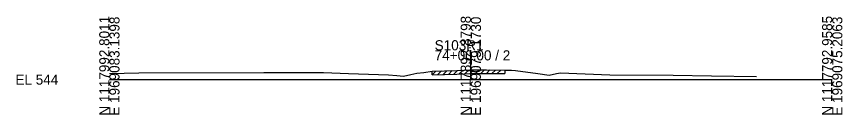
# Model space of a CAD drawing. Extents: x -26 to 203, y -10 to 12018.
# Drawn here: x -25.7 to 202.8, y 10990.3 to 11017.5 of the extents above; entities that cross this region are included whole.
import ezdxf

# ---------------------------------------------------------------- set-up
doc = ezdxf.new("R2010")
doc.units = 0
for name, color, linetype in [('Level 60', 7, 'Continuous'), ('Level 61', 7, 'Continuous'), ('Level 63', 7, 'Continuous')]:
    doc.layers.add(name, color=color, linetype=linetype)

msp = doc.modelspace()

# ---------------------------------------------------------------- linework, layer by layer
at = {"layer": 'Level 60'}
for p, q in [((0, 11001.69), (8.12, 11001.89)), ((8.12, 11001.89), (42.77, 11001.99)), ((42.77, 11001.99), (59.25, 11001.96)), ((59.25, 11001.96), (66.19, 11001.7)), ((66.19, 11001.7), (77.25, 11001.29)), ((83.44, 11001.38), (85.07, 11001.75)), ((85.07, 11001.75), (87.04, 11002.02)), ((87.04, 11002.02), (89.31, 11002.31)), ((89.31, 11002.31), (96.17, 11002.54)), ((96.17, 11002.54), (100, 11002.68)), ((100, 11002.68), (101.05, 11002.71)), ((101.05, 11002.71), (104.31, 11002.68)), ((104.31, 11002.68), (109.45, 11002.66)), ((109.45, 11002.66), (111.24, 11002.6)), ((111.24, 11002.6), (112.33, 11002.57)), ((112.33, 11002.57), (118.54, 11001.68)), ((118.54, 11001.68), (121.68, 11001.23)), ((121.68, 11001.23), (123.75, 11001.68)), ((123.75, 11001.68), (124.83, 11001.87)), ((124.83, 11001.87), (138.43, 11001.32)), ((77.25, 11001.29), (79.49, 11001.13)), ((79.49, 11001.13), (81.36, 11000.95)), ((81.36, 11000.95), (83.44, 11001.38)), ((138.43, 11001.32), (155.95, 11001.27)), ((155.95, 11001.27), (166.58, 11001.06)), ((166.58, 11001.06), (179.02, 11000.83))]:
    msp.add_line(p, q, dxfattribs=at)
at = {"layer": 'Level 61'}
for p, q in [((89.31, 11001.31), (90.35, 11002.35)), ((89.31, 11001.31), (89.31, 11002.31)), ((90.81, 11001.36), (91.85, 11002.4)), ((92.31, 11001.41), (93.35, 11002.45)), ((93.81, 11001.46), (94.85, 11002.5)), ((95.31, 11001.51), (96.35, 11002.55)), ((96.17, 11001.54), (100, 11001.68)), ((96.81, 11001.57), (97.85, 11002.6)), ((98.31, 11001.62), (99.35, 11002.65)), ((99.81, 11001.67), (100.85, 11002.71)), ((100, 11001.68), (101.05, 11001.71)), ((101.05, 11001.71), (104.31, 11001.68)), ((101.31, 11001.71), (102.3, 11002.7)), ((102.81, 11001.7), (103.8, 11002.69)), ((104.31, 11001.68), (105.31, 11002.68)), ((104.31, 11001.68), (109.45, 11001.66)), ((105.81, 11001.67), (106.81, 11002.67)), ((107.31, 11001.67), (108.31, 11002.66)), ((109.45, 11002.66), (109.45, 11001.66)), ((89.31, 11001.31), (96.17, 11001.54))]:
    msp.add_line(p, q, dxfattribs=at)
at = {"layer": 'Level 63'}
for p, q in [((100, 11000), (100, 11008.14)), ((0, 11000), (100, 11000)), ((100, 11000), (200, 11000))]:
    msp.add_line(p, q, dxfattribs=at)

# ---------------------------------------------------------------- texts
for s, p in [('N 1117992.8011', (0, 10990)), ('E 1969083.1398', (2.8, 10990)), ('N 1117892.8798', (100, 10990)), ('E 1969079.1730', (102.8, 10990)), ('N 1117792.9585', (200, 10990)), ('E 1969075.2063', (202.8, 10990))]:
    msp.add_text(s, height=2.8, rotation=90, dxfattribs=at).set_placement(p)
for s, p in [('S103R1', (90, 11008.14)), ('74+00.00 / 2', (90, 11005.34)), ('EL 544', (-26, 10998.6))]:
    msp.add_text(s, height=2.8, dxfattribs=at).set_placement(p)

doc.saveas('drawing.dxf')
